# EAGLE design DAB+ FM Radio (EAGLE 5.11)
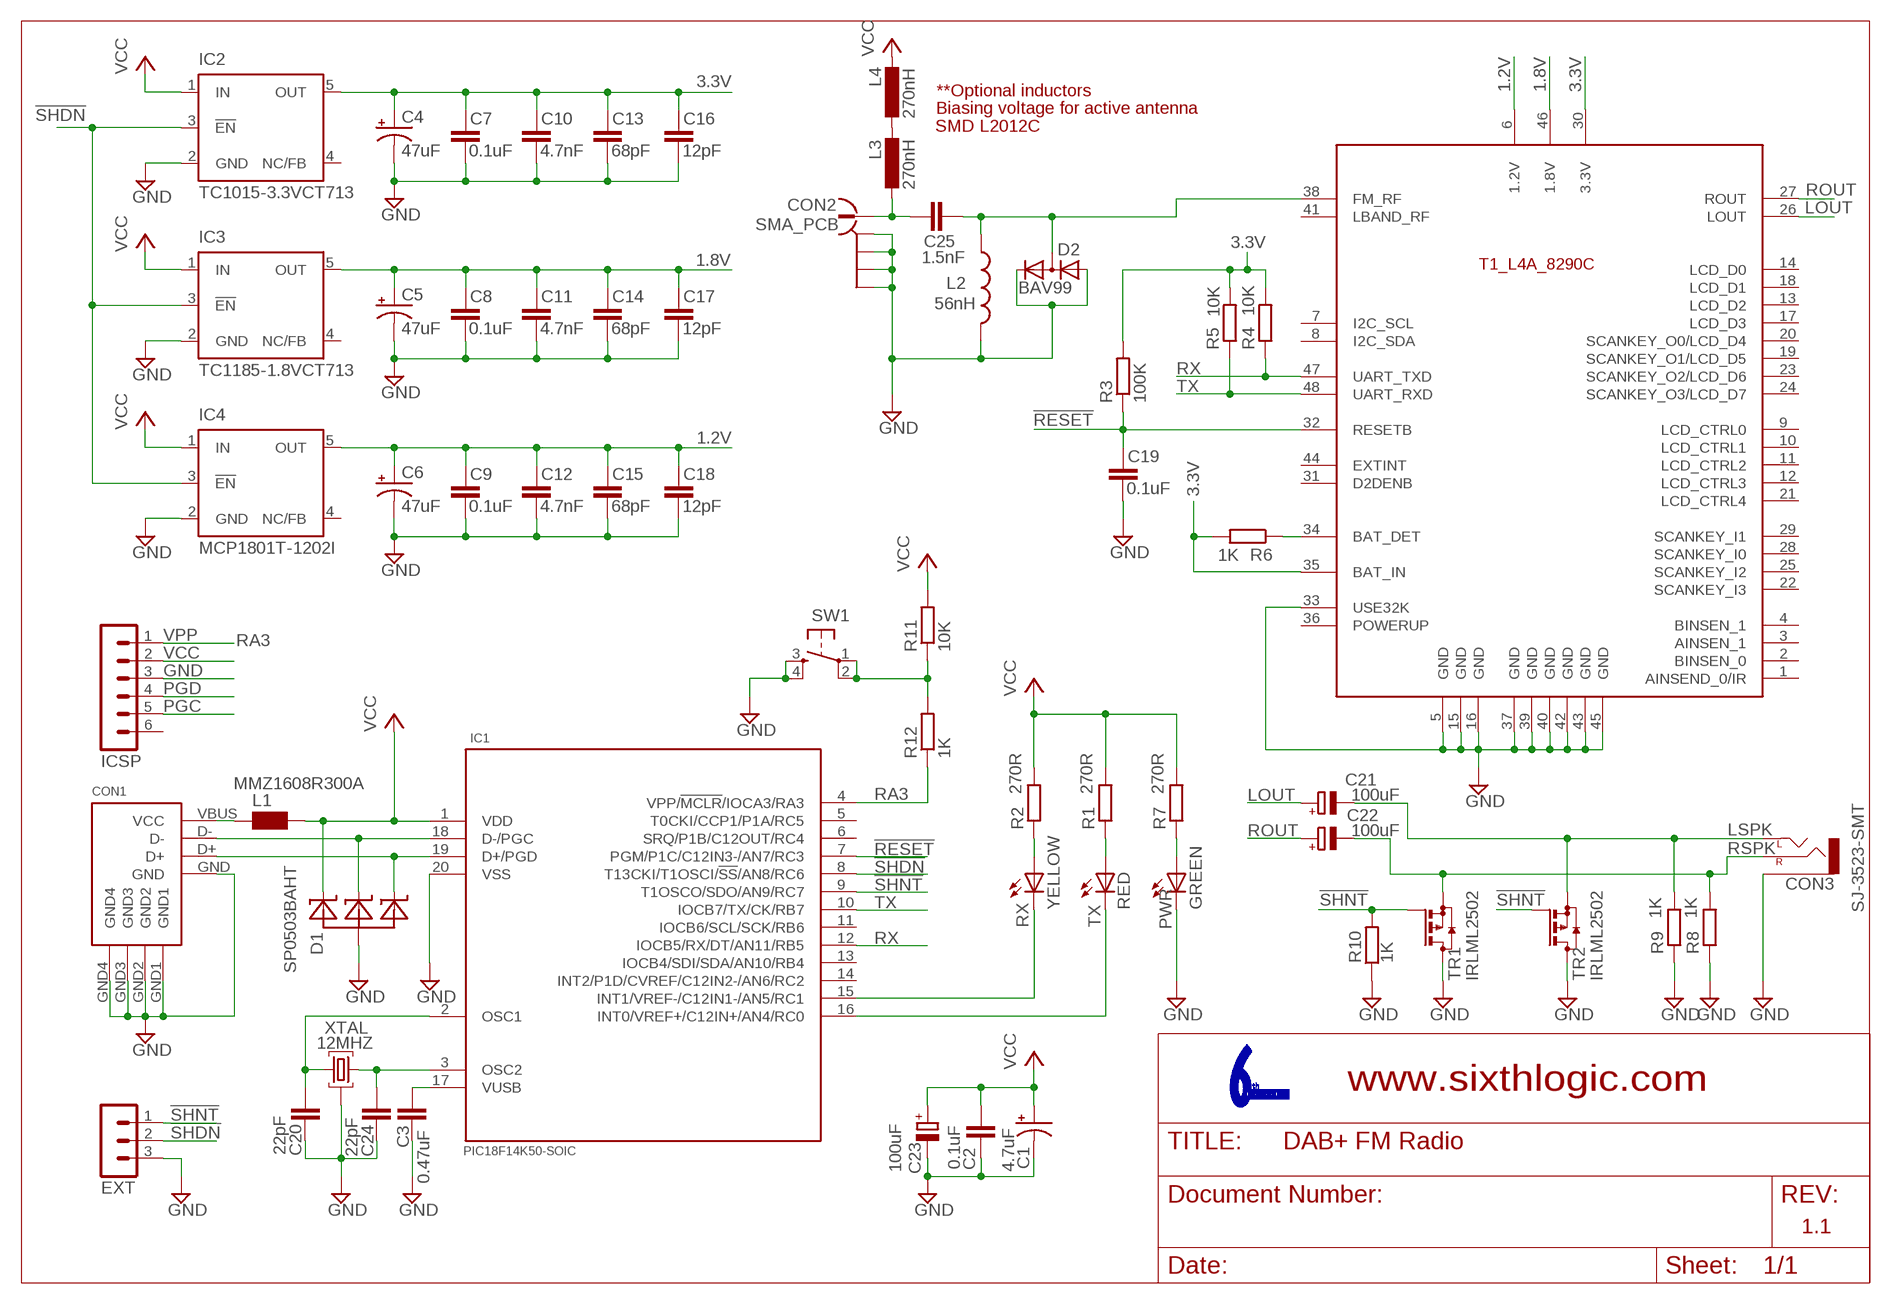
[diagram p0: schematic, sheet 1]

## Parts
C1  4.7uF  CAP_POL1206  [EIA3216]
C2  0.1uF  C-EUC0603  [C0603]
C3  0.47uF  C-EUC0603  [C0603]
C4  47uF  CAP_POL1206  [EIA3216]
C5  47uF  CAP_POL1206  [EIA3216]
C6  47uF  CAP_POL1206  [EIA3216]
C7  0.1uF  C-EUC0603  [C0603]
C8  0.1uF  C-EUC0603  [C0603]
C9  0.1uF  C-EUC0603  [C0603]
C10  4.7nF  C-EUC0603  [C0603]
C11  4.7nF  C-EUC0603  [C0603]
C12  4.7nF  C-EUC0603  [C0603]
C13  68pF  C-EUC0603  [C0603]
C14  68pF  C-EUC0603  [C0603]
C15  68pF  C-EUC0603  [C0603]
C16  12pF  C-EUC0603  [C0603]
C17  12pF  C-EUC0603  [C0603]
C18  12pF  C-EUC0603  [C0603]
C19  0.1uF  C-EUC0603  [C0603]
C20  22pF  C-EUC0603  [C0603]
C21  100uF  CPOL-EUD  [PANASONIC_D]
C22  100uF  CPOL-EUD  [PANASONIC_D]
C23  100uF  CPOL-EUD  [PANASONIC_D]
C24  22pF  C-EUC0603  [C0603]
C25  1.5nF  C-EUC0603  [C0603]
CON1  CON_MOLEX_USB_MINI_B  [MOLEX_USB_MINI_B]
CON2  SMA_PCB  [SMA_PCB]
CON3  SJ-3523-SMT  [SJ-3523-SMT]
D1  SP0503BAHT  [SOT143]
D2  BAV99  BAV199  [SOT23]
EXT  MA03-1  [MA03-1]
IC1  PIC18F14K50-SOIC  [SO20W]
IC2  TC1015-3.3VCT713  TPS77001  [SOT23-DBV]
IC3  TC1185-1.8VCT713  TPS77001  [SOT23-DBV]
IC4  MCP1801T-1202I  TPS77001  [SOT23-DBV]
ICSP  MA06-1  [MA06-1]
L1  MMZ1608R300A  WE-CBF_0603  [0603]
L2  56nH  INDUCTOR0603  [0603]
L3  270nH  L-EUL2012C  [L2012C]
L4  270nH  L-EUL2012C  [L2012C]
PWR  GREEN  LEDCHIP-LED0603  [CHIP-LED0603]
R1  270R  R-EU_R0603  [R0603]
R2  270R  R-EU_R0603  [R0603]
R3  100K  R-EU_R0603  [R0603]
R4  10K  R-EU_R0603  [R0603]
R5  10K  R-EU_R0603  [R0603]
R6  1K  R-EU_R0603  [R0603]
R7  270R  R-EU_R0603  [R0603]
R8  1K  R-EU_R0603  [R0603]
R9  1K  R-EU_R0603  [R0603]
R10  1K  R-EU_R0603  [R0603]
R11  10K  R-EU_R0603  [R0603]
R12  1K  R-EU_R0603  [R0603]
RX  YELLOW  LEDCHIP-LED0603  [CHIP-LED0603]
SW1  SCHURTER_PUSH_BUTTON  [PUSH_BUTTON_SMD]
TR1  IRLML2502  DMP2305U  [SOT23]
TR2  IRLML2502  DMP2305U  [SOT23]
TX  RED  LEDCHIP-LED0603  [CHIP-LED0603]
U$1  T1_L4A_8290C  [T1_L4A]
XTAL  12MHZ  [HC49US-G]

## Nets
1.2V: C6.A(+) C9.1 C12.1 C15.1 C18.1 IC4.5(OUT) U$1.6(1.2V)
1.8V: C5.A(+) C8.1 C11.1 C14.1 C17.1 IC3.5(OUT) U$1.46(1.8V)
3.3V: C4.A(+) C7.1 C10.1 C13.1 C16.1 IC2.5(OUT) R3.2 R4.2 R5.2 R6.2 U$1.30(3.3V) U$1.35(BAT_IN)
!RESET!: C19.1 IC1.7(PGM/P1C/C12IN3-/AN7/RC3) R3.1 U$1.32(RESETB)
!SHDN!: EXT.2 IC1.8(T13CKI/T1OSCI/!SS!/AN8/RC6) IC2.3(!EN) IC3.3(!EN) IC4.3(!EN)
!SHNT!: EXT.1 IC1.9(T1OSCO/SDO/AN9/RC7) R10.2 TR1.1(G) TR2.1(G)
FM_RF: C25.2 D2.3(AC) L2.1 U$1.38(FM_RF)
GND: C1.C(-) C2.2 C3.2 C4.C(-) C5.C(-) C6.C(-) C7.2 C8.2 C9.2 C10.2 C11.2 C12.2 C13.2 C14.2 C15.2 C16.2 C17.2 C18.2 C19.2 C20.2 C23.- C24.2 CON1.GND CON1.GND1 CON1.GND2 CON1.GND3 CON1.GND4 CON2.GND@1(GND) CON2.GND@2(GND) CON2.GND@3(GND) CON2.GND@4(GND) CON3.1(SLEEVE) D1.1 D2.1(A) D2.2(C) EXT.3 IC1.20(VSS) IC2.2(GND) IC3.2(GND) IC4.2(GND) ICSP.3 L2.2 PWR.C R8.1 R9.1 R10.1 SW1.3 SW1.4 TR1.3(D) TR2.3(D) U$1.5(GND) U$1.15(GND) U$1.16(GND) U$1.33(USE32K) U$1.37(GND) U$1.39(GND) U$1.40(GND) U$1.42(GND) U$1.43(GND) U$1.45(GND) XTAL.GND
LOUT: C21.+ U$1.26(LOUT)
LSPK: C21.- CON3.2(LEFT) R9.2 TR2.2(S)
N$1: PWR.A R7.1
N$2: CON1.VBUS(VCC) L1.1
N$3: R6.1 U$1.34(BAT_DET)
N$4: IC1.16(INT0/VREF+/C12IN+/AN4/RC0) TX.C
N$5: IC1.15(INT1/VREF-/C12IN1-/AN5/RC1) RX.C
N$6: C25.1 CON2.P$1 L3.2
N$7: C3.1 IC1.17(VUSB)
N$8: L3.1 L4.2
N$9: R1.1 TX.A
N$10: R2.1 RX.A
N$11: C20.1 IC1.2(OSC1) XTAL.2
N$12: C24.1 IC1.3(OSC2) XTAL.1
N$13: R11.1 R12.2 SW1.1 SW1.2
PGC: CON1.D- D1.3 IC1.18(D-/PGC) ICSP.5
PGD: CON1.D+ D1.4 IC1.19(D+/PGD) ICSP.4
RA3: IC1.4(VPP/!MCLR!/IOCA3/RA3) ICSP.1 R12.1
ROUT: C22.+ U$1.27(ROUT)
RSPK: C22.- CON3.3(RIGHT) R8.2 TR1.2(S)
RX: IC1.12(IOCB5/RX/DT/AN11/RB5) R4.1 U$1.47(UART_TXD)
TX: IC1.10(IOCB7/TX/CK/RB7) R5.1 U$1.48(UART_RXD)
VCC: C1.A(+) C2.1 C23.+ D1.2 IC1.1(VDD) IC2.1(IN) IC3.1(IN) IC4.1(IN) ICSP.2 L1.2 L4.1 R1.2 R2.2 R7.2 R11.2
Unconnected: IC1.5(T0CKI/CCP1/P1A/RC5) IC1.6(SRQ/P1B/C12OUT/RC4) IC1.11(IOCB6/SCL/SCK/RB6) IC1.13(IOCB4/SDI/SDA/AN10/RB4) IC1.14(INT2/P1D/CVREF/C12IN2-/AN6/RC2) IC2.4(NC/FB) IC3.4(NC/FB) IC4.4(NC/FB) ICSP.6 U$1.1(AINSEND_0/IR) U$1.2(BINSEN_0) U$1.3(AINSEN_1) U$1.4(BINSEN_1) U$1.7(I2C_SCL) U$1.8(I2C_SDA) U$1.9(LCD_CTRL0) U$1.10(LCD_CTRL1) U$1.11(LCD_CTRL2) U$1.12(LCD_CTRL3) U$1.13(LCD_D2) U$1.14(LCD_D0) U$1.17(LCD_D3) U$1.18(LCD_D1) U$1.19(SCANKEY_O1/LCD_D5) U$1.20(SCANKEY_O0/LCD_D4) U$1.21(LCD_CTRL4) U$1.22(SCANKEY_I3) U$1.23(SCANKEY_O2/LCD_D6) U$1.24(SCANKEY_O3/LCD_D7) U$1.25(SCANKEY_I2) U$1.28(SCANKEY_I0) U$1.29(SCANKEY_I1) U$1.31(D2DENB) U$1.36(POWERUP) U$1.41(LBAND_RF) U$1.44(EXTINT)

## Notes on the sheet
- **Optional inductors
- Biasing voltage for active antenna
- SMD L2012C
- VPP
- www.sixthlogic.com
- 1.1

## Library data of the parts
C1 C4-C6 = SparkFun:CAP_POL: Capacitor Polarized
C2 C3 C7-C20 C24 C25 = rcl:C-EU: CAPACITOR, European symbol
C21-C23 = rcl:CPOL-EU: POLARIZED CAPACITOR, European symbol
CON1 = Monkey:CON_MOLEX_USB_MINI_B
CON2 = Monkey:SMA_PCB: TE CONNECTIVITY - 5-1814832-1 - SOCKET, SMA, STRAIGHT PCB,50OHM Manufacturer: TE CONNECTIVITY Order Code: 1248990 Manufacturer Part No: 5-1814832-1 http://www.farnell.com/datasheets/316178.pdf
CON3 = Monkey:SJ-3523-SMT: SERIES: SJ-352X-SMT ? DESCRIPTION: 3.5 MM AUDIO JACKS http://products.cui.com/getpdf.aspx?fileID=7777
D1 = Monkey:SP0503BAHT: Surface Mount TVS Avalanche Diode Array http://www.littelfuse.com/data/en/Data_Sheets/SP05x_LeadFree.pdf
D2 = diode:BAV199: DIODE low-leakage double diode
EXT = con-lstb:MA03-1: PIN HEADER; OC_FARNELL: unknown; OC_NEWARK: unknown
IC1 = Monkey:PIC18F14K50: PIC18F/LF1XK50 20-Pin USB Flash Microcontrollers with nanoWatt XLP Technology. PIC18F13K50, PIC18LF13K50, PIC18F14K50, PIC18LF14K50. From: http://ww1.microchip.com/downloads/en/DeviceDoc/41350E.pdf
IC2-IC4 = texas:TPS770*: ULTRALOW-POWER 50-mA LOW-DROPOUT LINEAR REGULATORS 50-mA Low-Dropout Regulator Source: http://focus.ti.com/lit/ds/symlink/tps77001.pdf; MF: TEXAS INSTRUMENTS; MPN: TPS77001DBVT; OC_FARNELL: 8461554; OC_NEWARK: 77C1171
ICSP = con-lstb:MA06-1: PIN HEADER; OC_FARNELL: unknown; OC_NEWARK: unknown
L1 = wuerth-elektronik:WE-CBF: SMD EMI Suppression Ferrite Beads
L2 = SparkFun:INDUCTOR: Inductors
L3 L4 = resistor:L-EU: INDUCTOR, European symbol
PWR RX TX = led:LED: LED
R1-R10 = rcl:R-EU_: RESISTOR, European symbol
R11 R12 = resistor:R-EU_: RESISTOR, European symbol
SW1 = Monkey:SCHURTER_PUSH_BUTTON: SCHURTER - 1301.9316 - SWITCH, SMD, PUSH, 7MM Datasheet : http://www.schurterinc.com/pdf/english/typ_lph.pdf
TR1 TR2 = transistor-small-signal:DMP2305U
U$1 = Monkey:T1_L4A_8290C
XTAL = Monkey:12MHZ: HC/49US (AT49) 3RD LEAD CASE-GROUNDED SMD LOW PROFILE CRYSTAL CRYSTAL, 12MHz, 18pF, HC-49/US Source : http://www.abracon.com/Resonators/ABLSG.pdf

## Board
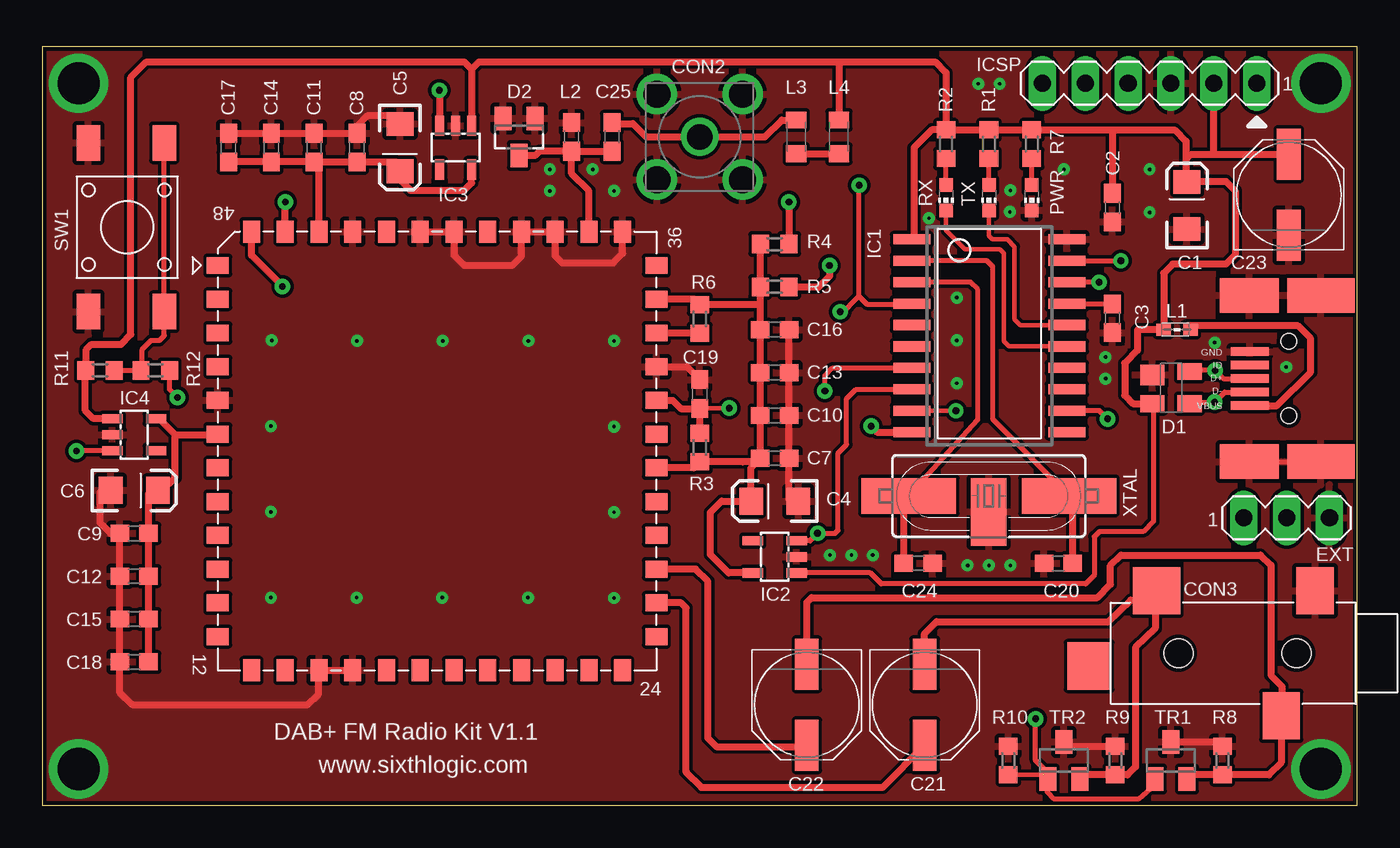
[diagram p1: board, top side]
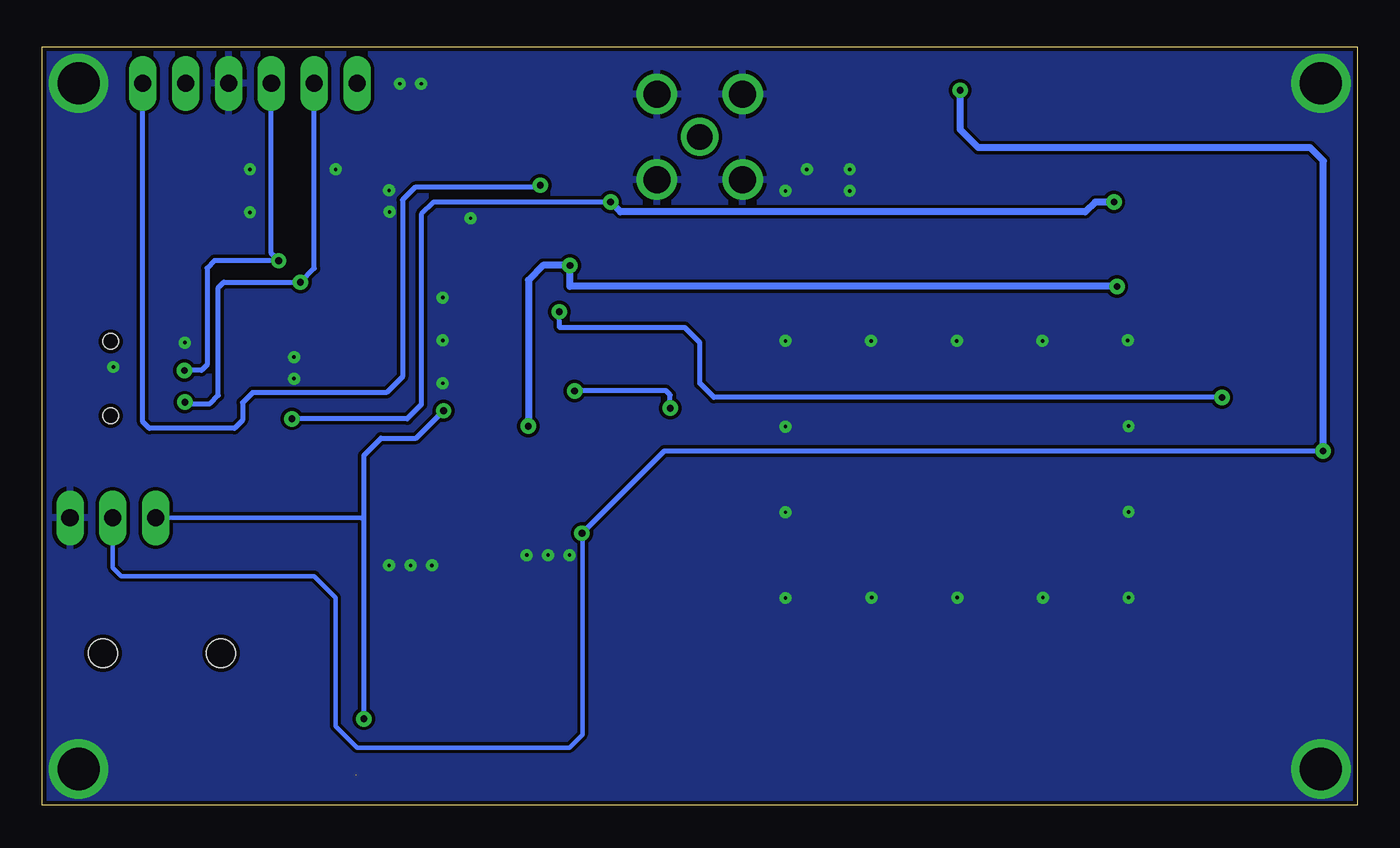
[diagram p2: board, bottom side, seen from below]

Size 77.98 x 44.96 mm. Coordinates in mm from the lower left corner, seen from the top.
Outline: 0,44.96 0,0 77.98,0 77.98,44.96 0,44.96
Copper layers (1*16): Top 0.035mm / dielectric 1.5mm / Bottom 0.035mm
Design rules "SparkFun": minimum track width 8mil, minimum drill 20mil, track to track 8mil, track to pad 8mil, pad to pad 8mil, via to via 8mil, smd to smd 8mil, copper to edge 10mil, drill to drill 8mil, minimum pad ring 12mil, minimum via ring 10mil, stop-mask expansion 4mil, vias tented up to drill 25mil, thermal gap 10mil

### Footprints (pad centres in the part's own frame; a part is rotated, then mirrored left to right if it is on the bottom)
EIA3216 = smd 1.4 x 1.6: A 1.4,0; C -1.4,0
C0603 = smd 1.1 x 1: 1 -0.85,0; 2 0.85,0
PANASONIC_D = smd 3 x 1.4: + 2.4,0; - -2.4,0
MOLEX_USB_MINI_B = smd 2.25 x 0.5: D+ 4.225,4.925; D- 4.225,5.725; GND 4.225,3.325; ID 4.225,4.125; VBUS 4.225,6.525 | smd 4 x 2.05: GND1 0,0; GND3 0,9.85 | smd 3.5 x 2.05: GND2 4.25,0; GND4 4.25,9.85 | hole 0.9: 1.9,2.725; 1.9,7.125
SMA_PCB = drill 1.6 round: GND@1 -2.54,2.54; GND@2 2.54,2.54; GND@3 -2.54,-2.54; GND@4 2.54,-2.54 | drill 1.5 round: P$1 0,0
SJ-3523-SMT = smd 2.2 x 2.8: 1 -1.1,-3.7; 3 0.9,3.7 | smd 2.8 x 2.8: 2 8.3,-3.7 | smd 2.6 x 2.8: 10 12.3,0.75 | hole 1.7: 0,0; 7,0
SOT143 = smd 1.2 x 1.44: 1 -0.75,-1.1 | smd 1 x 1.44: 2 0.95,-1.1; 3 0.95,1.1; 4 -0.95,1.1
SOT23 = smd 1 x 1.4: 1 -0.95,-1.1; 2 0.95,-1.1; 3 0,1.1
MA03-1 = drill 1.016 long: 1 -2.54,0; 2 0,0; 3 2.54,0
SO20W = smd 0.6 x 2.2: 1 -5.715,-4.6; 2 -4.445,-4.6; 3 -3.175,-4.6; 4 -1.905,-4.6; 5 -0.635,-4.6; 6 0.635,-4.6; 7 1.905,-4.6; 8 3.175,-4.6; 9 4.445,-4.6; 10 5.715,-4.6; 11 5.715,4.6; 12 4.445,4.6; 13 3.175,4.6; 14 1.905,4.6; 15 0.635,4.6; 16 -0.635,4.6; 17 -1.905,4.6; 18 -3.175,4.6; 19 -4.445,4.6; 20 -5.715,4.6
SOT23-DBV = smd 0.55 x 1.2: 1 -0.95,-1.3; 2 0,-1.3; 3 0.95,-1.3; 4 0.95,1.3; 5 -0.95,1.3
MA06-1 = drill 1.016 long: 1 -6.35,0; 2 -3.81,0; 3 -1.27,0; 4 1.27,0; 5 3.81,0; 6 6.35,0
0603 = smd 0.85 x 0.7: 1 -0.9,0; 2 0.7,0
0603' = smd 1.1 x 1: 1 -0.85,0; 2 0.85,0
L2012C = smd 1 x 1.2: 1 -1,0; 2 1,0
CHIP-LED0603 = smd 0.8 x 0.8: A 0,-0.75; C 0,0.75
R0603 = smd 1 x 1.1: 1 -0.85,0; 2 0.85,0
PUSH_BUTTON_SMD = smd 2.1 x 1.4: 1 0,4.5; 2 10,4.5; 3 0,0; 4 10,0
T1_L4A = smd 1.3 x 1: 1 0,0; 2 0,-2; 3 0,-4; 4 0,-6; 5 0,-8; 6 0,-10; 7 0,-12; 8 0,-14; 9 0,-16; 10 0,-18; 11 0,-20; 12 0,-22; 25 26,-22; 26 26,-20; 27 26,-18; 28 26,-16; 29 26,-14; 30 26,-12; 31 26,-10; 32 26,-8; 33 26,-6; 34 26,-4; 35 26,-2; 36 26,0 | smd 1 x 1.3: 13 2,-24; 14 4,-24; 15 6,-24; 16 8,-24; 17 10,-24; 18 12,-24; 19 14,-24; 20 16,-24; 21 18,-24; 22 20,-24; 23 22,-24; 24 24,-24; 37 24,2; 38 22,2; 39 20,2; 40 18,2; 41 16,2; 42 14,2; 43 12,2; 44 10,2; 45 8,2; 46 6,2; 47 4,2; 48 2,2
HC49US-G = smd 5.6 x 2.1: 1 -11.74,0.95; 2 -2.24,0.95 | smd 2.1 x 4: GND -6.99,0

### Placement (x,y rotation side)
C1  67.87,35.56 90 top
C2  63.45,35.43 270 top
C3  63.45,28.88 270 top
C4  43.43,18.03 180 top
C5  21.21,38.99 270 top
C6  5.46,18.67 0 top
C7  43.43,20.57 0 top
C8  18.67,38.99 90 top
C9  5.46,16.13 180 top
C10  43.43,23.11 0 top
C11  16.13,38.99 90 top
C12  5.46,13.59 180 top
C13  43.43,25.65 0 top
C14  13.59,38.99 90 top
C15  5.46,11.05 180 top
C16  43.43,28.19 0 top
C17  11.05,38.99 90 top
C18  5.46,8.51 180 top
C19  38.99,24.38 90 top
C20  60.25,14.35 180 top
C21  52.32,5.97 270 top
C22  45.34,5.97 270 top
C23  73.91,36.2 90 top
C24  51.94,14.35 0 top
C25  33.78,39.62 270 top
CON1  75.82,30.23 180 top
CON2  38.99,39.62 90 top
CON3  74.37,9.02 180 top
D1  66.93,24.77 270 top
D2  28.27,39.62 180 top
EXT  73.79,17.04 0 top
IC1  56.16,27.84 270 top
IC2  43.43,14.73 90 top
IC3  24.51,38.99 180 top
IC4  5.46,21.97 270 top
ICSP  65.66,42.8 180 top
L1  67.18,28.19 180 top
L2  56nH  [0603']  31.39,39.62 90 top
L3  44.7,39.62 90 top
L4  47.24,39.62 270 top
PWR  58.67,36.02 180 top
R1  56.13,39.19 90 top
R2  53.59,39.19 90 top
R3  38.99,21.21 270 top
R4  43.43,33.27 180 top
R5  43.43,30.73 180 top
R6  38.99,28.83 90 top
R7  58.67,39.19 90 top
R8  69.98,2.67 270 top
R9  63.63,2.67 270 top
R10  57.28,2.67 270 top
R11  3.43,25.78 180 top
R12  6.71,25.78 180 top
RX  53.59,36.02 180 top
SW1  2.74,39.27 270 top
TR1  66.93,2.67 0 top
TR2  60.58,2.67 0 top
TX  56.13,36.02 180 top
U$1  10.41,32 0 top
XTAL  63.12,17.4 0 top

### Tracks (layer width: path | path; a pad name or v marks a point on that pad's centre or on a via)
1.2V
  Top 0.406: C18.1 C15.1 C12.1 C9.1 6.31,18.46 C6.A 7.11,18.67 7.87,19.43 7.87,21.97 | IC4.5 6.92,22.92 7.87,21.97 | 7.87,21.97 10.38,21.97 U$1.6
1.8V
  Top 0.406: C17.1 C14.1 C11.1 | C11.1 C8.1 21,38.14 C5.A 21.21,37.08 21.84,36.45 25.02,36.45 25.46,36.89 IC3.5 | U$1.46 16.41,37.85 C11.1
3.3V
  Top 0.406: R4.2 R5.2 42.58,29.79 | 42.58,29.79 C16.1 C13.1 C10.1 C7.1 | IC2.5 40.7,13.78 39.62,14.86 39.62,17.37 40.28,18.03 C4.A 42.03,20.02 C7.1 | U$1.30 38.63,20 R3.2 41.53,20.36 | 41.53,20.36 42.37,20.36 C7.1 | 41.53,20.36 | U$1.35 38.66,30 R6.2 42.47,29.68 42.58,29.79
!RESET!  (via drill 0.4)
  Top 0.254: C19.1 40.73,23.53 v40.74,23.55
  Top 0.305: v46.41,24.56 46.41,25.48 46.86,25.93 IC1.7
  Top 0.406: R3.1 C19.1 38.98,23.52 37.87,23.52 37.39,24 U$1.32
  Bottom 0.305: v40.74,23.55 40.74,24.33 41,24.59 46.38,24.59 v46.41,24.56
!SHDN!  (via drill 0.4)
  Top 0.254: 2.05,21.02 v2.03,21.01
  Top 0.305: IC2.3 45.53,15.68 v45.97,16.13 47.02,16.13 47.19,16.31 47.19,20.88 47.7,21.39 47.7,24.11 48.26,24.66 IC1.8 | IC4.3 2.05,21.02
  Top 0.406: IC3.3 23.56,42.38 v23.55,42.39
  Bottom 0.254: EXT.2 73.79,14.1 73.28,13.59 61.85,13.59 60.58,12.32 60.58,4.7 59.31,3.43 46.71,3.43 45.95,4.19 45.95,16.1 v45.97,16.13
  Bottom 0.305: v2.03,21.01 41.1,21.01 v45.97,16.13
  Bottom 0.406: v23.55,42.39 23.55,40.06 22.48,38.99 2.79,38.99 2.01,38.2 2.01,21.03 v2.03,21.01
!SHNT!  (via drill 0.4)  (1 unrouted)
  Top 0.254: R10.2 59.36,1.82 59.36,2.21 | 65.98,1.23 TR1.1 | IC1.9 v54.18,23.39
  Top 0.305: 65.98,1.23 65.02,0.41 59.97,0.41 59.59,0.79 59.59,1.53 TR2.1 | 59.63,1.94 59.36,2.21 58.9,2.67 v58.9,5.13
  Top 0.406: TR2.1 59.38,1.82
  Bottom 0.254: EXT.1 59.05,17.04 58.9,16.89
  Bottom 0.305: v58.9,5.13 58.9,16.89 58.9,20.75 57.89,21.77 55.8,21.77 v54.18,23.39
FM_RF
  Top 0.406: L2.1 C25.2 | L2.1 29.48,38.77 29.21,38.51 28.29,38.51 D2.3 | U$1.38 32.41,36.42 31.39,37.44 L2.1
GND  (via drill 0.2, 2.5)
  Top 0.305: CON1.GND4 CON1.GND3
  Top 0.406: C6.C 3.43,18.54 3.43,16.76 4.06,16.13 C9.2 C12.2 C15.2 C18.2 4.61,6.69 5.33,5.97 15.75,5.97 16.38,6.6 16.38,7.97 U$1.15 U$1.16 | C17.2 C14.2 C11.2 C8.2 18.67,40.26 19.3,40.89 20.95,40.89 C5.C | U$1.43 U$1.42 24.41,32.61 25.02,32 27.89,32 28.42,32.54 U$1.40 U$1.39 30.41,32.58 30.84,32.16 33.86,32.16 34.42,32.72 U$1.37 | C16.2 C13.2 C10.2 C7.2 44.28,18.08 C4.C | U$1.33 38.22,26 C19.2 | TR1.3 69.73,3.77 R8.1 | R9.1 60.83,3.52 TR2.3
  other vias: 2.16,42.8 75.82,42.8 2.16,2.16 75.82,2.16 56.13,14.22 46.71,14.83 47.98,14.83 49.25,14.83 54.86,14.22 57.4,14.22 73.76,25.98 33.91,27.53 13.56,22.48 13.56,17.4 13.56,12.32 18.64,12.32 23.72,12.32 28.8,12.32 13.61,27.56 18.67,27.53 23.75,27.53 28.83,27.53 33.91,22.45 33.91,17.37 33.91,12.29 63.04,26.57 63.04,25.3 60.58,37.69 57.4,36.45 57.38,35.18 56.77,42.77 55.5,42.77 54.23,30.1 54.23,27.56 54.23,25.02 52.58,34.8 65.66,37.69 65.66,35.15 69.52,27.43 30.1,37.69 30.1,36.42 33.91,36.42 32.64,37.69
  pour Top: -0.38,45.34 -0.38,-0.38 78.36,-0.38 78.36,0.89 78.36,45.34
  pour Bottom: -0.38,45.34 -0.38,-0.38 78.36,-0.38 78.36,0.89 78.36,45.34
LOUT
  Top 0.406: U$1.26 37.88,12 38.18,11.71 38.18,2.03 38.15,2.01 39.09,1.07 49.85,1.07 C21.+
LSPK
  Top 0.305: CON3.2 65.99,12.48
  Top 0.406: TR2.2 61.78,1.82 R9.2 64.35,1.82 64.82,2.29 64.82,9.37 65.99,10.49 65.99,12.48 | CON3.2 65.7,12.19 64.54,12.17 63.22,10.9 53.03,10.9 52.32,10.18 C21.-
N$1
  Top 0.305: PWR.A R7.1
N$2
  Top 0.406: CON1.VBUS 73.21,23.7 75.21,25.68 75.21,27.69 74.47,28.42 67.88,28.42 L1.1
N$3
  Top 0.406: U$1.34 38.96,28 R6.1
N$4
  Top 0.254: TX.C 56.13,33.76 56.34,33.55 57.23,33.55 57.66,33.12 57.66,28.8 57.99,28.47 IC1.16
N$5
  Top 0.254: RX.C 53.59,34.09 54.71,32.97 56.79,32.97 57.02,32.74 57.02,27.51 57.33,27.2 IC1.15
N$6
  Top 0.406: L3.2 43.85,40.62 42.85,39.62 CON2.P$1 35.81,39.62 35.03,40.41 33.84,40.41 C25.1
N$7
  Top 0.305: C3.1 60.77,29.73 IC1.17
N$8
  Top 0.406: L3.1 L4.2
N$9
  Top 0.305: 56.13,38.56 R1.1 TX.A
N$10
  Top 0.305: 53.59,38.56 R2.1 RX.A
N$11
  Top 0.305: IC1.2 56.01,32.28 56.36,31.93 56.36,22.89 XTAL.2
  Top 0.406: C20.1 61.1,17.92 61.85,18.67 61.2,18.67 XTAL.2
N$12
  Top 0.305: IC1.3 55.04,31.01 55.47,30.58 55.47,22.85 XTAL.1
  Top 0.406: C24.1 51.09,18.06 XTAL.1
N$13
  Top 0.305: SW1.1 SW1.2 7.24,27.84 6.96,27.56 6.45,27.56 5.94,27.05 5.94,25.87 R12.2 | R11.1 R12.2 | R12.2 5.87,25.79
PGC  (via drill 0.4)
  Top 0.305: v62.66,31.01 IC1.18 | D1.3 68.12,23.9 v69.52,23.9 70.12,24.5 CON1.D-
  Bottom 0.305: v69.52,23.9 69.43,23.81 D1.3 67.54,24.3 67.54,30.68 67.21,31.01 v62.66,31.01 61.85,31.83 ICSP.5
PGD  (via drill 0.4)
  Top 0.305: IC1.19 v63.96,32.28 | D1.4 68.1,25.78 v69.55,25.78 70.03,25.3 CON1.D+
  Bottom 0.305: v69.55,25.78 68.53,25.78 68.2,26.11 68.2,31.85 67.77,32.28 v63.96,32.28 64.39,32.72 ICSP.4
RA3  (via drill 0.4)
  Top 0.305: 48.44,30.17 v48.44,36.75 | 48.44,30.17 48.89,29.72 51.53,29.72 IC1.4 | R12.1 7.56,24.65 v8.03,24.18 | v47.32,29.26 47.32,29.06 48.44,30.17
  Bottom 0.305: ICSP.1 72.01,22.73 71.63,22.35 66.57,22.35 66.09,22.83 66.09,23.88 65.51,24.46 57.56,24.46 56.62,25.4 56.62,35.89 55.88,36.63 48.56,36.63 v48.44,36.75 | v8.03,24.18 38.15,24.18 38.99,25.02 38.99,27.43 39.88,28.32 47.3,28.32 v47.32,29.26
ROUT
  Top 0.406: U$1.27 38.75,14 39.47,13.28 39.47,3.99 39.98,3.48 45.25,3.48 C22.+
RSPK
  Top 0.406: TR1.2 67.88,1.82 R8.2 72.73,1.82 73.46,2.54 73.46,5.15 CON3.3 73.51,5.2 73.51,7.06 72.85,7.72 72.85,14.25 72.24,14.83 63.96,14.83 63.35,14.22 63.35,13.11 62.56,12.32 45.62,12.32 45.34,12.04 C22.-
RX  (via drill 0.4)
  Top 0.305: IC1.12 62.69,23.39 v63.17,22.91
  Top 0.406: U$1.47 14.41,35.75 v14.43,35.76 | v44.27,35.76 44.27,33.29 R4.1
  Bottom 0.305: v63.17,22.91 56.34,22.91 55.5,23.75 55.5,35.03 54.76,35.76 v44.27,35.76 44.32,35.81
  Bottom 0.406: v14.43,35.76 15.54,35.76 16.13,35.18 43.69,35.18 v44.27,35.76
TX  (via drill 0.4)
  Top 0.406: IC1.10 49.5,22.12 v49.15,22.48 | R5.1 44.31,30.71 46.02,30.71 46.69,31.37 v46.69,32 | U$1.48 12.41,32.59 v14.25,30.76
  Bottom 0.406: v14.25,30.76 46.69,30.76 v46.69,32 48.28,32 49.15,31.14 v49.15,22.48
VCC
  Top 0.305: IC2.1 49.11,13.78 49.76,13.13 61.87,13.13 62.38,13.64 62.38,15.93 62.69,16.23 65.28,16.23 65.89,16.84 65.89,23.76 D1.2
  Top 0.406: D1.2 64.68,23.81 64.19,24.31 64.19,26.21 64.95,26.97 64.95,28.17 64.97,28.19 L1.2 | L1.2 | R2.2 R1.2 R7.2 63.42,40.04 | IC4.1 3.04,22.92 2.56,23.39 2.56,25.77 R11.2 2.62,25.82 2.62,27.03 2.92,27.33 4.67,27.33 5.26,27.91 5.26,43.16 6.17,44.07 25.02,44.07 25.46,43.63 | 25.46,43.63 IC3.1 | L1.2 66.5,28.17 66.5,31.55 67.03,32.08 70.18,32.08 70.74,32.64 70.74,36.42 70.18,36.98 67.89,36.98 C1.A | 69.34,38.59 68.11,38.59 67.82,38.3 | 69.34,38.59 C23.+ | 67.82,38.3 67.82,37.01 C1.A | C1.A 67.57,37.26 | ICSP.2 69.47,38.72 69.34,38.59 | R2.2 53.59,43.43 52.96,44.07 47.19,44.07 | 47.19,44.07 25.9,44.07 25.46,43.63 | R2.2 52.74,40.04 51.69,38.99 51.69,33.68 IC1.1 | 63.42,40.04 67.15,40.04 67.82,39.37 67.82,38.3 | C2.1 63.45,40.02 63.42,40.04 | L4.1 47.24,44.02 47.19,44.07

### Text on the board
tPlace: DAB+ FM Radio Kit V1.1 | www.sixthlogic.com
